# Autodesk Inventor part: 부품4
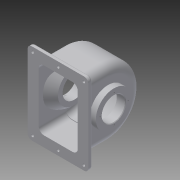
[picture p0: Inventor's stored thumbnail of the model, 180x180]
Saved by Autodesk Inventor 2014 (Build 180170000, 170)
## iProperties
Created: 2015-09
Part Number: 부품4
Material: Generic
Document SubType Name: Modeling
Designer: pms2
Density: 1 g/cm^3
Appearance: Default
Author: pms2
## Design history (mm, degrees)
sketch "스케치1"
  geometry: L1 (-43.5, 0)-(43.5, 0); L2 (43.5, 0)-(43.5, 20); L3 (43.5, 20)-(28.5, 20); L4 (28.5, 20)-(28.5, 42); L5 (19.5, 51)-(-29.5, 51); L6 (-38.5, 42)-(-38.5, 39.747); L7 (-38.5, 39.747)-(-24.5, 28); L8 (-24.5, 28)-(-24.5, 20); L9 (-24.5, 20)-(-40.5, 20); L10 (-40.5, 20)-(-40.5, 33); L11 (-40.5, 33)-(-39.611, 33); L12 (-43.5, 43)-(-43.5, 0); L13 (-39.29, 33.883)-(-43.5, 37.416); L14 (43.5, 20)-(43.5, 31); L15 (43.5, 31)-(33.5, 31); L16 (33.5, 31)-(33.5, 43); L17 (33.5, 57)-(-43.5, 57); L18 (33.5, 43)-(33.5, 57); L19 (-43.5, 43)-(-43.5, 57); A1 r 0.5 centre (-39.611, 33.5) between (-39.611, 33) and (-39.29, 33.883); A2 r 9 centre (-29.5, 42) between (-29.5, 51) and (-38.5, 42); A3 r 9 centre (19.5, 42) between (28.5, 42) and (19.5, 51); 2 further points
  constraints: 38 end point, 12 parallel, 6 point on circle, 6 tangent, 5 perpendicular, 3 centre point, 1 coincident, 1 equal radius, 1 horizontal, 1 horizontal alignment, 1 midpoint, 1 point on line
  dimensions: "d9" = 87 distance of L1.start L1.end; "d10" = 67 distance between parallel lines of L4 L6; "d11" = 5 distance between parallel lines of L16 L4; "d13" = 5 distance between parallel lines of L7 L13; "d14" = 5 distance between parallel lines of L12 L6; "d15" = 16 distance of L8.end L9.end; "d16" = 3 distance between parallel lines of L12 L10; "d17" = 50 deg angle of L7 L8; "d18" = 40 diameter of L3 L1; "d19" = 62 diameter of L15 L1; "d20" = 102 diameter of L5 L1; "d21" = 114 diameter of L17 L1; "d22" = 40 diameter of L9 L1; "d23" = 66 diameter of L11 L1; "d24" = 56 diameter of L7.end L1; "d25" = 0.5 radius of A1; "d26" = 9 radius of A2; "d41" = 14 distance of L12.start L17.end; "d42" = 14 distance of L16.end L17.start
revolve "회전1" sketch "스케치1" stored, may be unused: angle "d28" = 90 deg
chamfer "모따기1" distance "d29" = 1; stored, may be unused: second distance "d30" = 1, angle "d31" = 45 deg
chamfer "모따기2" distance "d32" = 1; stored, may be unused: second distance "d33" = 1, angle "d34" = 45 deg
node "작업 평면1"
sketch "스케치2"
  geometry: L1 (-46.5, 70)-(57.5, 70); L2 (57.5, 70)-(57.5, -70); L3 (57.5, -70)-(-46.5, -70); L4 (-46.5, -70)-(-46.5, 70); L5 (-43.5, 31)-(-43.5, -31) reference; 2 further points
  constraints: 8 end point, 2 parallel, 1 horizontal, 1 horizontal alignment, 1 midpoint, 1 perpendicular
  dimensions: "d36" = 3 distance between parallel lines of L4 L5; "d37" = 104 distance of L1.start L1.end; "d38" = 140 distance of L1.end L2.end
extrude "돌출1" join sketch "스케치2" distance "d39" = 7; taper "d40" = 0 deg
sketch "스케치3"
  geometry: L1 (32.249, -47)-(-32.249, -47) reference; L2 (-32.249, -47)-(32.249, -47); L3 (-32.249, -47)-(32.249, -47); A1 r 57 centre (0, 0) between (-32.249, -47) and (32.249, -47) reference; A2 r 57 centre (0, 0) between (-32.249, -47) and (32.249, -47)
  constraints: 4 end point, 2 collinear, 2 point on circle, 1 centre point, 1 coincident, 1 concentric
extrude "돌출2" cut sketch "스케치3" stored distance "d43" = 7; taper "d44" = 0 deg
sketch "스케치4"
  geometry: L1 (-40.608, -40)-(40.608, -40) reference; L2 (57, 0)-(57, -40); L3 (40.608, -40)-(57, -40); C1 r 31 at (0, 0) reference; A1 r 57 centre (0, 0) between (40.608, -40) and (-40.608, -40) reference; A2 r 57 centre (0, 0) between (40.608, -40) and (57, 0)
  constraints: 5 end point, 3 point on circle, 2 perpendicular, 1 centre point, 1 coincident, 1 concentric, 1 tangent
extrude "돌출3" join sketch "스케치4" stored distance "d45" = 7; taper "d46" = 0 deg
sketch "스케치5"
  geometry: L1 (0, 0)-(0, 40) reference; L2 (-114, 40)-(-114, 0); L3 (-97.608, 0)-(-114, 0); C1 r 31 at (-57, 40) reference; A1 r 57 centre (-57, 40) between (0, 40) and (-97.608, 0) reference; A2 r 57 centre (-57, 40) between (-114, 40) and (-97.608, 0)
  constraints: 5 end point, 3 point on circle, 1 centre point, 1 coincident, 1 parallel, 1 perpendicular, 1 tangent
extrude "돌출4" join sketch "스케치5" stored distance "d47" = 7; taper "d48" = 0 deg
fillet "모깎기1" dims "d49" = 14
fillet "모깎기2" dims "d50" = 7
sketch "스케치6"
  geometry: L1 (-57.5, 63)-(-57.5, -63) reference; L2 (-50.5, -70)-(39.5, -70) reference; 2 further points
  dimensions: "d51" = 8 distance from line of L1 point (-49.5, -62); "d52" = 8 distance from line of L2 point (-49.5, -62)
hole "구멍1" sketch "스케치6" at (-49.5, -62) diameter "d53" = 5; stored, may be unused: countersink angle "d57" = 90 deg, drill point angle "d59" = 118 deg; dims "d54" = 6, "d55" = 4, "d56" = 2, "d58" = 8
fillet "모깎기3" dims "d66" = 3
sketch "스케치7"
  geometry: C1 r 31 at (0, 0) reference; 1 further point
  constraints: 1 vertical alignment
  dimensions: "d67" = 24 distance of C1.centre point (0, 24)
hole "구멍2" sketch "스케치7" at (0, 24) diameter "d68" = 2.459; stored, may be unused: countersink angle "d72" = 90 deg, drill point angle "d74" = 118 deg; dims "d69" = 6, "d70" = 4, "d71" = 2, "d73" = 8
sketch "스케치8"
  geometry: C1 r 20 at (0, 0) reference; 1 further point
  dimensions: "d78" = 28 distance of C1.centre point (0, 28)
hole "구멍3" sketch "스케치8" at (0, 28) diameter "d79" = 2.459; stored, may be unused: countersink angle "d83" = 90 deg, drill point angle "d85" = 118 deg; dims "d80" = 7, "d81" = 4, "d82" = 2, "d84" = 9
sketch "스케치9"
  geometry: L1 (57, 0)-(63, 0); L2 (63, 0)-(63, -7.395); L3 (57, 0)-(52.624, 0); L4 (63, -7.395)-(52.624, -9.224); L5 (63, -7.395)-(73.537, -7.395); L6 (52.624, 0)-(52.624, -9.224); A1 r 57 centre (0, 0) between (0, -57) and (0, 57) reference; A2 r 51 centre (0, 0) between (-40, -31.639) and (-40, 31.639) reference; 1 further point
  constraints: 12 end point, 3 perpendicular, 2 horizontal, 1 equal length, 1 point on circle
  dimensions: "d89" = 7.39482 distance of L1.end L2.end; "d90" = 170 deg angle of L4 L5; "d91" = 6 distance of L1.start L1.end; "d92" = 9.22447 distance of L3.end L4.end
revolve "회전2" sketch "스케치9" stored, may be unused: angle "d93" = 90 deg
sketch "스케치10"
  geometry: C1 r 7.395 at (0, 0) reference; 1 further point
  constraints: 1 coincident
hole "구멍4" sketch "스케치10" at (0, 0) diameter "d94" = 4.459; stored, may be unused: countersink angle "d98" = 90 deg, drill point angle "d100" = 118 deg; dims "d95" = 7, "d96" = 4, "d97" = 2, "d99" = 9
fillet "모깎기4" dims "d101" = 3
sketch "스케치11"
  geometry: L1 (-29.5, 57)-(19.5, 57) reference; L2 (33.5, 43)-(33.5, -43) reference; L3 (19.5, -57)-(-29.5, -57) reference; L4 (-43.5, 43)-(-43.5, -43) reference; L5 (-29.5, 52)-(19.5, 52); L6 (28.5, 43)-(28.5, -43); L7 (19.5, -52)-(-29.5, -52); L8 (-38.5, -43)-(-38.5, 43); A1 r 9 centre (-29.5, -43) between (-38.5, -43) and (-29.5, -52); A2 r 9 centre (19.5, -43) between (19.5, -52) and (28.5, -43); A3 r 9 centre (19.5, 43) between (28.5, 43) and (19.5, 52); A4 r 9 centre (-29.5, 43) between (-29.5, 52) and (-38.5, 43); 1 further point
  constraints: 8 end point, 8 point on circle, 8 tangent, 4 centre point, 3 equal radius, 2 parallel, 1 horizontal, 1 perpendicular
  dimensions: "d102" = 5 distance between parallel lines of L2 L6; "d103" = 5 distance between parallel lines of L4 L8; "d104" = 5 distance between parallel lines of L3 L7; "d105" = 5 distance between parallel lines of L1 L5; "d106" = 9 radius of A1
extrude "돌출5" cut sketch "스케치11" stored distance "d107" = 7; taper "d108" = 0 deg
sketch "스케치12"
  geometry: L1 (-29.5, -31.639)-(19.5, -31.639) reference; L2 (28.5, -43)-(28.5, -12.806) reference; L3 (-38.5, -12.806)-(-38.5, -43); L4 (28.5, -12.806)-(28.5, -43); L5 (19.5, -52)-(-29.5, -52); A1 r 9 centre (-29.5, -43) between (-38.5, -43) and (-29.5, -52) reference; A2 r 9 centre (19.5, -43) between (19.5, -52) and (28.5, -43) reference; A3 r 9 centre (19.5, -43) between (19.5, -52) and (28.5, -43); A4 r 9 centre (-29.5, -43) between (-38.5, -43) and (-29.5, -52); 1 further point
  constraints: 6 end point, 4 point on circle, 4 tangent, 2 centre point, 2 coincident, 2 concentric, 2 equal length, 1 perpendicular, 2 other
extrude "돌출6" cut sketch "스케치12" distance "d109" = 40; taper "d110" = 0 deg
sketch "스케치13"
  geometry: L1 (-38.5, 43)-(-38.5, 12.806) reference; L2 (19.5, 31.639)-(-29.5, 31.639) reference; L3 (-29.5, 52)-(19.5, 52); L4 (28.5, 12.806)-(28.5, 43); L5 (-38.5, 12.806)-(-38.5, 43); A1 r 9 centre (19.5, 43) between (28.5, 43) and (19.5, 52) reference; A2 r 9 centre (-29.5, 43) between (-29.5, 52) and (-38.5, 43) reference; A3 r 9 centre (-29.5, 43) between (-29.5, 52) and (-38.5, 43); A4 r 9 centre (19.5, 43) between (28.5, 43) and (19.5, 52); 1 further point
  constraints: 6 end point, 4 point on circle, 4 tangent, 2 centre point, 2 coincident, 2 equal length, 1 perpendicular, 2 other
extrude "돌출7" cut sketch "스케치13" distance "d111" = 40; taper "d112" = 0 deg
node "솔리드1"
pattern_linear "직사각형 패턴1" dims "d62" = 44, "d65" = 124
pattern_circular "원형 패턴1" dims angle "d76" = 360 deg
pattern_circular "원형 패턴2" dims angle "d87" = 360 deg
other parameters: "d35" = -47
